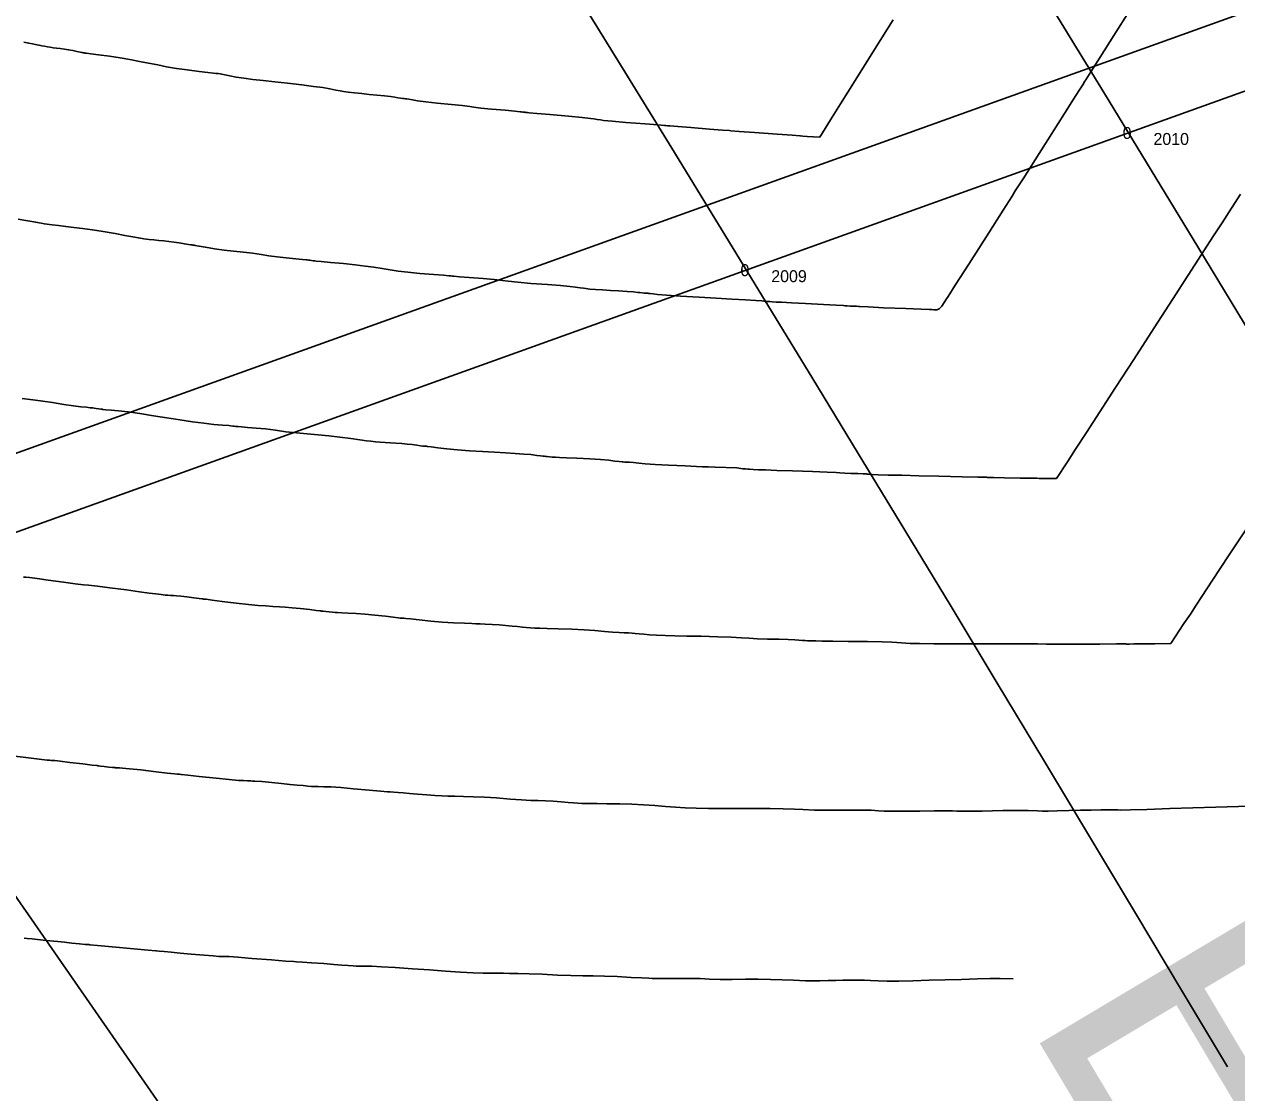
# Model space of a CAD drawing. Extents: x 74655 to 77873, y 48844 to 50507.
# Drawn here: x 75194.38 to 75206.57, y 49698.68 to 49709.42 of the extents above; entities that cross this region are included whole.
import ezdxf

# ---------------------------------------------------------------- set-up
doc = ezdxf.new("R2010")
doc.units = 0
for name, color, linetype in [('2', 7, 'Continuous'), ('5', 7, 'Continuous'), ('50', 7, 'Continuous'), ('62', 7, 'Continuous'), ('7', 7, 'Continuous')]:
    doc.layers.add(name, color=color, linetype=linetype)

msp = doc.modelspace()

# ---------------------------------------------------------------- linework, layer by layer
at = {"layer": '2'}
for radius in [833.511, 829.511, 818.511]:
    msp.add_arc((74494.001, 49274.129), radius, 30.805045, 46.697858, dxfattribs=at)
at = {"layer": '5'}
msp.add_line((75166.591, 49740.588), (75280.568, 49576.243), dxfattribs=at)
at = {"layer": '50'}
for points in [[(75203.654, 49706.661), (75203.669, 49706.685), (75203.741, 49706.798), (75203.878, 49707.012), (75204.079, 49707.327), (75204.224, 49707.555), (75204.313, 49707.695), (75204.346, 49707.747), (75204.424, 49707.869), (75204.546, 49708.061), (75204.712, 49708.324), (75204.841, 49708.527), (75204.932, 49708.67), (75204.986, 49708.755), (75205.024, 49708.815), (75205.047, 49708.852), (75205.056, 49708.865), (75205.107, 49708.946), (75205.2, 49709.094), (75205.337, 49709.31), (75205.494, 49709.558)], [(75203.117, 49709.468), (75202.93, 49709.17), (75202.736, 49708.859), (75202.589, 49708.623), (75202.488, 49708.461), (75202.378, 49708.287)], [(75194.371, 49709.242), (75194.421, 49709.232), (75194.459, 49709.227)], [(75202.378, 49708.287), (75202.251, 49708.296), (75202.208, 49708.299), (75202.184, 49708.3), (75202.179, 49708.301), (75202.101, 49708.307), (75201.949, 49708.318), (75201.722, 49708.334), (75201.567, 49708.345), (75201.484, 49708.352), (75201.471, 49708.354), (75201.401, 49708.36), (75201.271, 49708.37), (75201.083, 49708.384), (75200.95, 49708.395), (75200.871, 49708.401), (75200.847, 49708.403), (75200.83, 49708.404), (75200.82, 49708.405), (75200.817, 49708.405), (75200.751, 49708.411), (75200.622, 49708.421), (75200.429, 49708.436), (75200.289, 49708.448), (75200.204, 49708.457), (75200.173, 49708.462), (75200.14, 49708.467), (75200.107, 49708.472), (75200.073, 49708.477), (75199.988, 49708.486), (75199.851, 49708.499), (75199.663, 49708.516), (75199.532, 49708.527), (75199.456, 49708.534), (75199.437, 49708.536), (75199.421, 49708.537), (75199.41, 49708.539), (75199.402, 49708.54), (75199.392, 49708.541), (75199.379, 49708.543), (75199.365, 49708.544), (75199.31, 49708.549), (75199.213, 49708.558), (75199.075, 49708.57), (75198.97, 49708.581), (75198.897, 49708.59), (75198.857, 49708.597), (75198.782, 49708.606), (75198.673, 49708.617), (75198.529, 49708.631), (75198.416, 49708.643), (75198.333, 49708.654), (75198.282, 49708.662), (75198.246, 49708.669), (75198.225, 49708.672), (75198.219, 49708.673), (75198.21, 49708.675), (75198.197, 49708.676), (75198.181, 49708.678), (75198.161, 49708.68), (75198.135, 49708.684), (75198.105, 49708.69), (75198.06, 49708.696), (75197.999, 49708.703), (75197.923, 49708.711), (75197.847, 49708.718), (75197.772, 49708.726), (75197.697, 49708.734), (75197.636, 49708.741), (75197.589, 49708.748), (75197.555, 49708.754), (75197.509, 49708.762), (75197.45, 49708.773), (75197.38, 49708.786), (75197.285, 49708.799), (75197.167, 49708.814), (75197.025, 49708.83), (75196.896, 49708.844), (75196.78, 49708.857), (75196.676, 49708.869), (75196.585, 49708.881), (75196.507, 49708.893), (75196.443, 49708.905), (75196.395, 49708.915), (75196.362, 49708.921), (75196.346, 49708.924), (75196.326, 49708.927), (75196.304, 49708.93), (75196.279, 49708.933), (75196.222, 49708.94), (75196.134, 49708.95), (75196.015, 49708.965), (75195.906, 49708.98), (75195.807, 49708.996), (75195.718, 49709.014), (75195.627, 49709.032), (75195.534, 49709.05), (75195.439, 49709.069), (75195.339, 49709.087), (75195.233, 49709.103), (75195.123, 49709.117), (75195.045, 49709.127), (75195.001, 49709.132), (75194.99, 49709.134), (75194.979, 49709.135), (75194.968, 49709.137), (75194.958, 49709.139), (75194.937, 49709.144), (75194.905, 49709.15), (75194.863, 49709.159), (75194.821, 49709.167), (75194.779, 49709.173), (75194.737, 49709.179), (75194.699, 49709.184), (75194.666, 49709.188), (75194.638, 49709.192), (75194.61, 49709.196), (75194.581, 49709.202), (75194.552, 49709.208), (75194.525, 49709.213), (75194.501, 49709.218), (75194.459, 49709.227)], [(75206.611, 49707.715), (75206.496, 49707.536), (75206.426, 49707.427), (75206.334, 49707.285), (75206.22, 49707.109), (75206.086, 49706.9), (75205.927, 49706.654), (75205.744, 49706.372), (75205.538, 49706.053), (75205.355, 49705.771), (75205.196, 49705.526), (75205.061, 49705.318), (75204.953, 49705.151), (75204.871, 49705.024), (75204.76, 49704.854)], [(75203.654, 49706.661), (75203.607, 49706.587), (75203.581, 49706.563), (75203.555, 49706.552), (75203.527, 49706.553), (75203.505, 49706.554), (75203.49, 49706.554), (75203.481, 49706.554), (75203.4, 49706.558), (75203.246, 49706.564), (75203.02, 49706.573), (75202.865, 49706.58), (75202.782, 49706.584), (75202.769, 49706.585), (75202.749, 49706.587), (75202.72, 49706.588), (75202.683, 49706.59), (75202.654, 49706.592), (75202.631, 49706.593), (75202.616, 49706.595), (75202.544, 49706.599), (75202.417, 49706.606), (75202.234, 49706.615), (75202.093, 49706.622), (75201.994, 49706.627), (75201.939, 49706.63), (75201.899, 49706.632), (75201.876, 49706.634), (75201.869, 49706.634), (75201.861, 49706.635), (75201.853, 49706.636), (75201.844, 49706.636), (75201.832, 49706.637), (75201.815, 49706.639), (75201.795, 49706.642), (75201.734, 49706.646), (75201.633, 49706.652), (75201.493, 49706.66), (75201.336, 49706.668), (75201.165, 49706.678), (75200.977, 49706.689), (75200.838, 49706.698), (75200.747, 49706.705), (75200.704, 49706.711), (75200.674, 49706.715), (75200.657, 49706.717), (75200.652, 49706.718), (75200.643, 49706.718), (75200.629, 49706.719), (75200.611, 49706.72), (75200.591, 49706.722), (75200.57, 49706.725), (75200.548, 49706.727), (75200.504, 49706.731), (75200.44, 49706.736), (75200.354, 49706.741), (75200.272, 49706.747), (75200.194, 49706.752), (75200.121, 49706.757), (75200.064, 49706.761), (75200.024, 49706.765), (75200.002, 49706.768), (75199.967, 49706.772), (75199.922, 49706.779), (75199.865, 49706.786), (75199.771, 49706.796), (75199.64, 49706.806), (75199.472, 49706.818), (75199.34, 49706.829), (75199.245, 49706.839), (75199.187, 49706.847), (75199.102, 49706.856), (75198.991, 49706.866), (75198.853, 49706.877), (75198.756, 49706.884), (75198.698, 49706.889), (75198.681, 49706.89), (75198.666, 49706.892), (75198.654, 49706.893), (75198.646, 49706.894), (75198.593, 49706.899), (75198.496, 49706.907), (75198.355, 49706.918), (75198.235, 49706.929), (75198.136, 49706.941), (75198.056, 49706.953), (75197.975, 49706.966), (75197.891, 49706.979), (75197.806, 49706.992), (75197.705, 49707.005), (75197.588, 49707.017), (75197.456, 49707.029), (75197.364, 49707.037), (75197.311, 49707.042), (75197.298, 49707.043), (75197.283, 49707.045), (75197.267, 49707.047), (75197.25, 49707.05), (75197.235, 49707.052), (75197.223, 49707.054), (75197.213, 49707.055), (75197.174, 49707.058), (75197.107, 49707.064), (75197.011, 49707.073), (75196.92, 49707.083), (75196.836, 49707.095), (75196.758, 49707.108), (75196.673, 49707.12), (75196.581, 49707.13), (75196.482, 49707.14), (75196.386, 49707.152), (75196.291, 49707.165), (75196.198, 49707.181), (75196.133, 49707.193), (75196.095, 49707.199), (75196.084, 49707.201), (75196.073, 49707.203), (75196.063, 49707.204), (75196.052, 49707.205), (75196.027, 49707.209), (75195.987, 49707.215), (75195.933, 49707.225), (75195.881, 49707.233), (75195.829, 49707.239), (75195.779, 49707.245), (75195.729, 49707.25), (75195.68, 49707.255), (75195.631, 49707.26), (75195.579, 49707.267), (75195.525, 49707.275), (75195.467, 49707.286), (75195.389, 49707.3), (75195.29, 49707.318), (75195.171, 49707.339), (75195.061, 49707.357), (75194.963, 49707.371), (75194.874, 49707.381), (75194.793, 49707.39), (75194.721, 49707.398), (75194.656, 49707.405), (75194.579, 49707.416), (75194.491, 49707.432), (75194.391, 49707.451), (75194.315, 49707.465)], [(75201.544, 49704.961), (75201.328, 49704.969), (75201.255, 49704.972), (75201.218, 49704.974), (75201.216, 49704.974), (75201.212, 49704.974), (75201.207, 49704.974), (75201.2, 49704.974), (75201.14, 49704.977), (75201.025, 49704.982), (75200.857, 49704.989), (75200.723, 49704.995), (75200.623, 49705.003), (75200.558, 49705.01), (75200.506, 49705.015), (75200.466, 49705.018), (75200.439, 49705.019), (75200.418, 49705.021), (75200.401, 49705.022), (75200.39, 49705.023), (75200.362, 49705.026), (75200.318, 49705.031), (75200.258, 49705.038), (75200.174, 49705.045), (75200.066, 49705.052), (75199.934, 49705.058), (75199.832, 49705.063), (75199.761, 49705.067), (75199.721, 49705.069), (75199.687, 49705.071), (75199.66, 49705.073), (75199.638, 49705.076), (75199.622, 49705.078), (75199.611, 49705.079), (75199.605, 49705.079), (75199.599, 49705.08), (75199.595, 49705.08), (75199.592, 49705.08), (75199.57, 49705.083), (75199.531, 49705.088), (75199.473, 49705.095), (75199.402, 49705.101), (75199.316, 49705.107), (75199.217, 49705.113), (75199.107, 49705.119), (75198.986, 49705.126), (75198.854, 49705.133), (75198.734, 49705.142), (75198.628, 49705.153), (75198.535, 49705.165), (75198.469, 49705.173), (75198.432, 49705.178), (75198.422, 49705.18), (75198.411, 49705.181), (75198.399, 49705.182), (75198.387, 49705.182), (75198.362, 49705.185), (75198.326, 49705.189), (75198.279, 49705.196), (75198.228, 49705.201), (75198.173, 49705.206), (75198.115, 49705.209), (75198.059, 49705.213), (75198.006, 49705.216), (75197.957, 49705.22), (75197.908, 49705.224), (75197.862, 49705.229), (75197.818, 49705.235), (75197.751, 49705.244), (75197.662, 49705.256), (75197.551, 49705.272), (75197.441, 49705.285), (75197.331, 49705.295), (75197.222, 49705.303), (75197.114, 49705.313), (75197.007, 49705.326), (75196.902, 49705.341), (75196.803, 49705.353), (75196.71, 49705.363), (75196.623, 49705.369), (75196.562, 49705.374), (75196.525, 49705.377), (75196.514, 49705.378), (75196.502, 49705.379), (75196.488, 49705.381), (75196.474, 49705.383), (75196.435, 49705.387), (75196.371, 49705.392), (75196.282, 49705.399), (75196.181, 49705.41), (75196.067, 49705.426), (75195.94, 49705.445), (75195.81, 49705.465), (75195.676, 49705.486), (75195.538, 49705.508), (75195.421, 49705.524), (75195.325, 49705.536), (75195.25, 49705.543), (75195.197, 49705.547), (75195.167, 49705.55), (75195.159, 49705.551), (75195.145, 49705.553), (75195.125, 49705.556), (75195.098, 49705.56), (75195.079, 49705.563), (75195.066, 49705.565), (75195.061, 49705.565), (75195.039, 49705.567), (75195.001, 49705.571), (75194.946, 49705.576), (75194.871, 49705.586), (75194.775, 49705.6), (75194.659, 49705.619), (75194.563, 49705.634), (75194.489, 49705.644), (75194.436, 49705.649), (75194.356, 49705.66)], [(75201.544, 49704.961), (75201.605, 49704.954), (75201.631, 49704.952), (75201.654, 49704.949), (75201.672, 49704.948), (75201.708, 49704.945), (75201.761, 49704.943), (75201.832, 49704.941), (75201.946, 49704.937), (75202.104, 49704.932), (75202.306, 49704.925), (75202.453, 49704.919), (75202.545, 49704.915), (75202.582, 49704.911), (75202.631, 49704.908), (75202.691, 49704.906), (75202.763, 49704.904), (75202.814, 49704.902), (75202.846, 49704.901), (75202.856, 49704.9), (75202.87, 49704.899), (75202.887, 49704.897), (75202.907, 49704.895), (75202.967, 49704.893), (75203.066, 49704.89), (75203.205, 49704.887), (75203.376, 49704.883), (75203.577, 49704.878), (75203.81, 49704.873), (75203.969, 49704.869), (75204.055, 49704.867), (75204.067, 49704.866), (75204.128, 49704.865), (75204.237, 49704.862), (75204.396, 49704.86), (75204.503, 49704.858), (75204.558, 49704.857), (75204.561, 49704.857), (75204.585, 49704.856), (75204.63, 49704.855), (75204.76, 49704.854)], [(75206.706, 49704.4), (75206.492, 49704.076), (75206.331, 49703.832), (75206.223, 49703.667), (75206.166, 49703.582), (75206.107, 49703.492), (75206.043, 49703.396), (75205.91, 49703.195)], [(75199.155, 49703.385), (75199.012, 49703.39), (75198.963, 49703.392), (75198.937, 49703.393), (75198.933, 49703.394), (75198.928, 49703.394), (75198.924, 49703.394), (75198.92, 49703.395), (75198.88, 49703.396), (75198.804, 49703.399), (75198.693, 49703.404), (75198.58, 49703.411), (75198.465, 49703.421), (75198.347, 49703.434), (75198.263, 49703.443), (75198.213, 49703.448), (75198.196, 49703.449), (75198.177, 49703.45), (75198.158, 49703.452), (75198.138, 49703.454), (75198.088, 49703.46), (75198.01, 49703.469), (75197.903, 49703.481), (75197.804, 49703.49), (75197.715, 49703.497), (75197.634, 49703.501), (75197.572, 49703.504), (75197.528, 49703.507), (75197.504, 49703.508), (75197.476, 49703.51), (75197.444, 49703.513), (75197.408, 49703.518), (75197.383, 49703.52), (75197.369, 49703.522), (75197.365, 49703.522), (75197.36, 49703.523), (75197.356, 49703.523), (75197.35, 49703.524), (75197.314, 49703.528), (75197.249, 49703.536), (75197.153, 49703.548), (75197.07, 49703.556), (75196.999, 49703.562), (75196.942, 49703.566), (75196.877, 49703.569), (75196.807, 49703.573), (75196.73, 49703.578), (75196.631, 49703.587), (75196.509, 49703.601), (75196.366, 49703.619), (75196.265, 49703.632), (75196.207, 49703.64), (75196.192, 49703.642), (75196.179, 49703.643), (75196.169, 49703.644), (75196.162, 49703.644), (75196.134, 49703.648), (75196.083, 49703.654), (75196.01, 49703.664), (75195.951, 49703.671), (75195.906, 49703.676), (75195.876, 49703.677), (75195.846, 49703.679), (75195.819, 49703.681), (75195.792, 49703.683), (75195.753, 49703.687), (75195.7, 49703.694), (75195.634, 49703.703), (75195.535, 49703.716), (75195.403, 49703.734), (75195.238, 49703.757), (75195.111, 49703.773), (75195.023, 49703.783), (75194.972, 49703.787), (75194.887, 49703.797), (75194.769, 49703.813), (75194.617, 49703.834), (75194.504, 49703.85), (75194.429, 49703.859), (75194.393, 49703.862), (75194.368, 49703.864)], [(75205.91, 49703.195), (75205.75, 49703.193), (75205.675, 49703.192), (75205.605, 49703.191), (75205.54, 49703.191), (75205.493, 49703.19), (75205.464, 49703.19), (75205.454, 49703.191), (75205.365, 49703.191), (75205.197, 49703.19), (75204.95, 49703.189), (75204.778, 49703.188), (75204.681, 49703.189), (75204.659, 49703.19), (75204.568, 49703.191), (75204.407, 49703.192), (75204.178, 49703.192), (75204.024, 49703.192), (75203.947, 49703.192), (75203.945, 49703.192), (75203.941, 49703.192), (75203.935, 49703.192), (75203.925, 49703.192), (75203.854, 49703.192), (75203.721, 49703.192), (75203.526, 49703.193), (75203.381, 49703.194), (75203.288, 49703.196), (75203.245, 49703.199), (75203.201, 49703.202), (75203.154, 49703.206), (75203.105, 49703.209), (75203.007, 49703.212), (75202.86, 49703.215), (75202.663, 49703.217), (75202.511, 49703.219), (75202.403, 49703.22), (75202.339, 49703.221), (75202.289, 49703.222), (75202.254, 49703.223), (75202.232, 49703.225), (75202.204, 49703.227), (75202.169, 49703.23), (75202.127, 49703.233), (75202.06, 49703.236), (75201.969, 49703.238), (75201.854, 49703.24), (75201.753, 49703.244), (75201.665, 49703.248), (75201.592, 49703.254), (75201.487, 49703.26), (75201.352, 49703.264), (75201.186, 49703.268), (75201.042, 49703.271), (75200.921, 49703.274), (75200.822, 49703.276), (75200.737, 49703.279), (75200.666, 49703.284), (75200.61, 49703.289), (75200.562, 49703.293), (75200.522, 49703.297), (75200.491, 49703.3), (75200.454, 49703.302), (75200.41, 49703.304), (75200.36, 49703.305), (75200.295, 49703.309), (75200.214, 49703.316), (75200.117, 49703.325), (75200.007, 49703.333), (75199.883, 49703.339), (75199.746, 49703.343), (75199.638, 49703.347), (75199.561, 49703.349), (75199.513, 49703.351), (75199.468, 49703.354), (75199.426, 49703.357), (75199.387, 49703.361), (75199.339, 49703.366), (75199.283, 49703.371), (75199.155, 49703.385)], [(75194.196, 49702.073), (75194.39, 49702.048), (75194.527, 49702.031), (75194.606, 49702.022), (75194.628, 49702.021), (75194.648, 49702.019), (75194.666, 49702.018), (75194.682, 49702.018), (75194.738, 49702.012), (75194.833, 49702), (75194.966, 49701.984), (75195.058, 49701.973), (75195.108, 49701.967), (75195.116, 49701.966), (75195.122, 49701.966), (75195.125, 49701.965), (75195.126, 49701.965), (75195.144, 49701.963), (75195.178, 49701.959), (75195.228, 49701.953), (75195.264, 49701.949), (75195.286, 49701.947), (75195.295, 49701.946), (75195.311, 49701.945), (75195.334, 49701.944), (75195.363, 49701.943), (75195.435, 49701.936), (75195.547, 49701.924), (75195.702, 49701.906), (75195.815, 49701.893), (75195.886, 49701.885), (75195.915, 49701.882), (75195.937, 49701.88), (75195.952, 49701.878), (75195.959, 49701.878), (75196.021, 49701.871), (75196.136, 49701.859), (75196.306, 49701.84), (75196.437, 49701.827), (75196.53, 49701.819), (75196.583, 49701.817), (75196.62, 49701.815), (75196.639, 49701.815), (75196.641, 49701.814), (75196.645, 49701.814), (75196.65, 49701.814), (75196.656, 49701.813), (75196.672, 49701.812), (75196.697, 49701.811), (75196.766, 49701.808)], [(75204.57, 49701.512), (75204.476, 49701.516), (75204.375, 49701.516), (75204.22, 49701.515), (75204.012, 49701.511), (75203.858, 49701.51), (75203.759, 49701.51), (75203.714, 49701.512), (75203.637, 49701.513), (75203.528, 49701.512), (75203.386, 49701.511), (75203.275, 49701.509), (75203.196, 49701.509), (75203.149, 49701.508), (75203.111, 49701.508), (75203.083, 49701.508), (75203.064, 49701.509), (75203.027, 49701.511), (75202.971, 49701.514), (75202.896, 49701.518), (75202.788, 49701.521), (75202.647, 49701.521), (75202.473, 49701.52), (75202.327, 49701.521), (75202.21, 49701.525), (75202.123, 49701.53), (75202.011, 49701.533), (75201.877, 49701.535), (75201.718, 49701.535), (75201.611, 49701.535), (75201.556, 49701.535), (75201.551, 49701.536), (75201.546, 49701.536), (75201.541, 49701.536), (75201.534, 49701.536), (75201.485, 49701.536), (75201.393, 49701.536), (75201.259, 49701.537), (75201.136, 49701.539), (75201.026, 49701.544), (75200.928, 49701.55), (75200.826, 49701.557), (75200.718, 49701.565), (75200.606, 49701.573), (75200.488, 49701.579), (75200.366, 49701.582), (75200.238, 49701.584), (75200.139, 49701.585), (75200.069, 49701.586), (75200.028, 49701.586), (75199.986, 49701.588), (75199.944, 49701.59), (75199.902, 49701.593), (75199.847, 49701.597), (75199.778, 49701.603), (75199.697, 49701.609), (75199.618, 49701.614), (75199.543, 49701.617), (75199.471, 49701.618), (75199.378, 49701.623), (75199.264, 49701.631), (75199.128, 49701.642), (75199.005, 49701.65), (75198.894, 49701.655), (75198.795, 49701.657), (75198.709, 49701.659), (75198.637, 49701.661), (75198.577, 49701.662), (75198.507, 49701.666), (75198.425, 49701.672), (75198.332, 49701.681), (75198.253, 49701.688), (75198.188, 49701.694), (75198.137, 49701.698), (75198.094, 49701.702), (75198.058, 49701.704), (75198.03, 49701.705), (75197.959, 49701.71), (75197.845, 49701.72), (75197.689, 49701.735), (75197.56, 49701.746), (75197.46, 49701.753), (75197.388, 49701.755), (75197.331, 49701.757), (75197.29, 49701.758), (75197.265, 49701.759), (75197.228, 49701.762), (75197.18, 49701.766), (75197.12, 49701.772), (75197.047, 49701.779), (75196.962, 49701.788), (75196.766, 49701.808)], [(75204.57, 49701.512), (75204.62, 49701.51), (75204.677, 49701.511), (75204.767, 49701.512), (75204.889, 49701.515), (75205.003, 49701.518), (75205.109, 49701.52), (75205.208, 49701.522), (75205.278, 49701.524), (75205.32, 49701.524), (75205.334, 49701.524), (75205.353, 49701.523), (75205.377, 49701.522), (75205.406, 49701.521), (75205.504, 49701.523), (75205.669, 49701.527), (75205.902, 49701.535), (75206.133, 49701.542), (75206.363, 49701.549), (75206.592, 49701.556), (75206.746, 49701.561), (75206.825, 49701.564), (75206.832, 49701.563)], [(75194.375, 49700.233), (75194.404, 49700.23), (75194.454, 49700.225), (75194.594, 49700.21)], [(75194.594, 49700.21), (75194.713, 49700.198), (75194.779, 49700.191), (75194.853, 49700.183), (75194.933, 49700.175), (75194.99, 49700.17), (75195.024, 49700.167), (75195.034, 49700.166), (75195.113, 49700.159), (75195.26, 49700.145), (75195.477, 49700.125), (75195.623, 49700.111), (75195.699, 49700.104), (75195.706, 49700.104), (75195.734, 49700.102), (75195.783, 49700.097), (75195.854, 49700.091), (75195.945, 49700.082), (75196.055, 49700.072), (75196.184, 49700.061), (75196.277, 49700.053), (75196.333, 49700.048), (75196.352, 49700.048), (75196.376, 49700.047), (75196.404, 49700.047), (75196.436, 49700.046), (75196.523, 49700.04), (75196.665, 49700.029), (75196.862, 49700.013), (75197.003, 49700.002), (75197.088, 49699.996), (75197.116, 49699.995), (75197.176, 49699.992), (75197.267, 49699.985), (75197.388, 49699.976), (75197.49, 49699.968), (75197.572, 49699.961), (75197.635, 49699.957), (75197.683, 49699.953), (75197.716, 49699.952), (75197.735, 49699.951), (75197.767, 49699.951), (75197.813, 49699.95), (75197.872, 49699.95), (75197.97, 49699.945), (75198.107, 49699.937), (75198.282, 49699.924), (75198.451, 49699.912), (75198.612, 49699.901), (75198.765, 49699.891), (75198.892, 49699.884), (75198.992, 49699.88), (75199.066, 49699.88), (75199.116, 49699.88), (75199.143, 49699.88), (75199.147, 49699.88), (75199.152, 49699.88), (75199.157, 49699.879), (75199.164, 49699.879), (75199.198, 49699.879), (75199.258, 49699.878), (75199.346, 49699.878), (75199.455, 49699.875), (75199.586, 49699.869), (75199.74, 49699.86), (75199.876, 49699.855), (75199.995, 49699.852), (75200.098, 49699.852), (75200.213, 49699.85), (75200.341, 49699.845), (75200.482, 49699.838), (75200.588, 49699.832), (75200.659, 49699.829), (75200.693, 49699.827), (75200.727, 49699.826), (75200.758, 49699.825), (75200.788, 49699.826), (75200.837, 49699.826), (75200.906, 49699.827), (75200.994, 49699.828), (75201.084, 49699.827), (75201.176, 49699.825), (75201.27, 49699.821), (75201.377, 49699.818), (75201.498, 49699.818), (75201.632, 49699.821), (75201.76, 49699.82), (75201.882, 49699.818), (75202.114, 49699.808)], [(75204.324, 49699.824), (75204.192, 49699.827), (75204.094, 49699.827), (75203.964, 49699.824), (75203.803, 49699.818), (75203.641, 49699.813), (75203.478, 49699.808), (75203.315, 49699.803), (75203.174, 49699.801), (75203.058, 49699.801), (75202.966, 49699.804), (75202.89, 49699.807), (75202.83, 49699.809), (75202.787, 49699.81), (75202.736, 49699.811), (75202.678, 49699.81), (75202.611, 49699.809), (75202.539, 49699.807), (75202.462, 49699.805), (75202.379, 49699.803), (75202.304, 49699.803), (75202.235, 49699.804), (75202.114, 49699.808)]]:
    msp.add_lwpolyline(points, dxfattribs=at)
at = {"layer": '7'}
for p, q in [((74992.787, 49632.792), (75369.276, 49767.909)), ((74993.04, 49632.087), (75369.529, 49767.203))]:
    msp.add_line(p, q, dxfattribs=at)

# ---------------------------------------------------------------- texts
at = {"layer": '2'}
msp.add_text('E', height=3, rotation=300.805, dxfattribs=at).set_placement((75204.424, 49699.457))
at = {"layer": '62'}
for s, p in [('0', (75205.426, 49708.27)), ('2010', (75205.736, 49708.21)), ('0', (75201.581, 49706.89)), ('2009', (75201.891, 49706.83))]:
    msp.add_text(s, height=0.12, dxfattribs=at).set_placement(p)

doc.saveas('drawing.dxf')
